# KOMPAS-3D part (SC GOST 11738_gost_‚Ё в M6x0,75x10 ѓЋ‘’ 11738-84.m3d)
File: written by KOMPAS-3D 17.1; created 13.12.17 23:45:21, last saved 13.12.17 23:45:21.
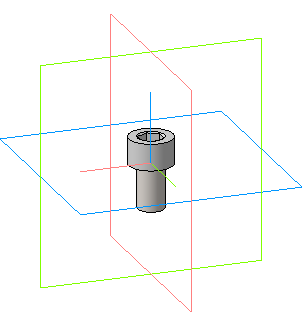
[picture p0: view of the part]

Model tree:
1. Операция без истории:1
